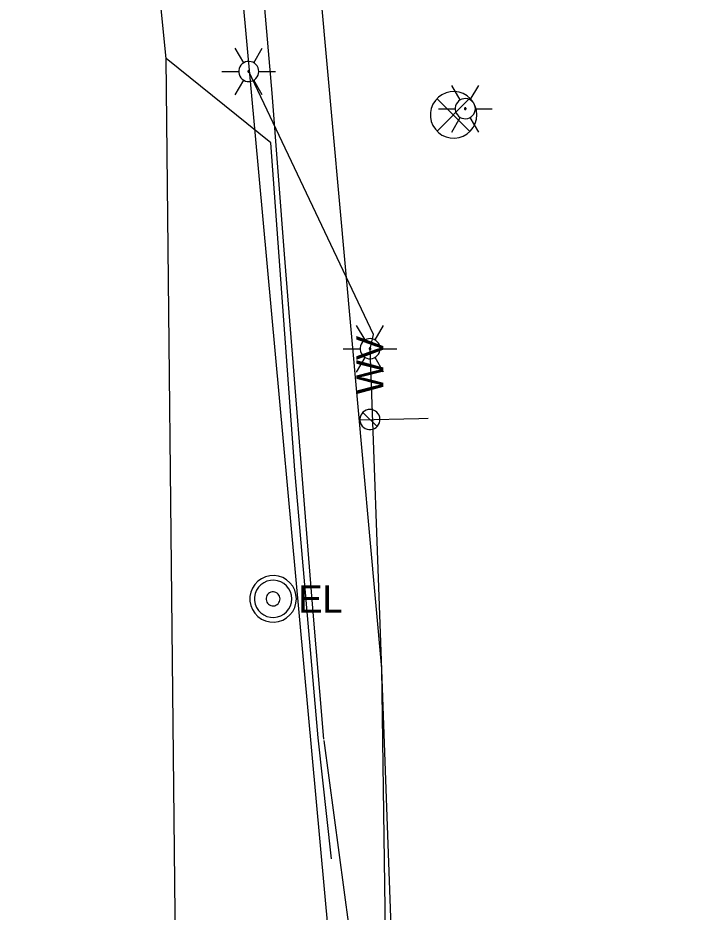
# Model space of a CAD drawing. Extents: x 600849 to 606371, y 330010 to 403088.
# Drawn here: x 605046.3 to 605141.7, y 332769.8 to 332896.4 of the extents above; entities that cross this region are included whole.
import ezdxf

# ---------------------------------------------------------------- set-up
doc = ezdxf.new("R2010")
doc.units = 0
for name, color, linetype in [('E_LTG', 7, 'Continuous'), ('E_LTG_CID', 7, 'Continuous'), ('E_SIG', 7, 'Continuous'), ('E_UTL_E', 7, 'Continuous'), ('E_UTL_G_UG', 7, 'Continuous'), ('E_UTL_SAN_UG', 7, 'Continuous'), ('E_UTL_TV_UG', 7, 'Continuous'), ('E_UTL_W', 7, 'Continuous'), ('E_UTL_W_UG', 7, 'Continuous')]:
    doc.layers.add(name, color=color, linetype=linetype)

msp = doc.modelspace()

# ---------------------------------------------------------------- linework, layer by layer
at = {"layer": 'E_LTG'}
for points in [[(605078.31, 332890.08), (605077.11, 332892.14)], [(605079.73, 332890.08), (605080.93, 332892.14)], [(605080.45, 332888.84), (605080.42, 332889.11), (605080.35, 332889.38), (605080.22, 332889.62), (605080.05, 332889.83), (605079.85, 332890.01), (605079.61, 332890.14), (605079.36, 332890.23), (605079.09, 332890.27), (605078.82, 332890.26), (605078.55, 332890.19), (605078.31, 332890.08), (605078.08, 332889.92), (605077.9, 332889.73), (605077.75, 332889.5), (605077.65, 332889.25), (605077.6, 332888.98), (605077.6, 332888.71), (605077.65, 332888.44), (605077.75, 332888.19), (605077.9, 332887.96), (605078.08, 332887.76), (605078.31, 332887.61), (605078.55, 332887.49), (605078.82, 332887.43), (605079.09, 332887.42), (605079.36, 332887.46), (605079.61, 332887.54), (605079.85, 332887.68), (605080.05, 332887.86), (605080.22, 332888.07), (605080.35, 332888.31), (605080.42, 332888.57), (605080.45, 332888.84)], [(605080.45, 332888.84), (605080.42, 332889.11), (605080.35, 332889.38), (605080.22, 332889.62), (605080.05, 332889.83), (605079.85, 332890.01), (605079.61, 332890.14), (605079.36, 332890.23), (605079.09, 332890.27), (605078.82, 332890.26), (605078.55, 332890.19), (605078.31, 332890.08), (605078.08, 332889.92), (605077.9, 332889.73), (605077.75, 332889.5), (605077.65, 332889.25), (605077.6, 332888.98), (605077.6, 332888.71), (605077.65, 332888.44), (605077.75, 332888.19), (605077.9, 332887.96), (605078.08, 332887.76), (605078.31, 332887.61), (605078.55, 332887.49), (605078.82, 332887.43), (605079.09, 332887.42), (605079.36, 332887.46), (605079.61, 332887.54), (605079.85, 332887.68), (605080.05, 332887.86), (605080.22, 332888.07), (605080.35, 332888.31), (605080.42, 332888.57), (605080.45, 332888.84)], [(605080.45, 332888.84), (605080.42, 332889.11), (605080.35, 332889.38), (605080.22, 332889.62), (605080.05, 332889.83), (605079.85, 332890.01), (605079.61, 332890.14), (605079.36, 332890.23), (605079.09, 332890.27), (605078.82, 332890.26), (605078.55, 332890.19), (605078.31, 332890.08), (605078.08, 332889.92), (605077.9, 332889.73), (605077.75, 332889.5), (605077.65, 332889.25), (605077.6, 332888.98), (605077.6, 332888.71), (605077.65, 332888.44), (605077.75, 332888.19), (605077.9, 332887.96), (605078.08, 332887.76), (605078.31, 332887.61), (605078.55, 332887.49), (605078.82, 332887.43), (605079.09, 332887.42), (605079.36, 332887.46), (605079.61, 332887.54), (605079.85, 332887.68), (605080.05, 332887.86), (605080.22, 332888.07), (605080.35, 332888.31), (605080.42, 332888.57), (605080.45, 332888.84)], [(605075.21, 332888.84), (605077.59, 332888.84)], [(605079.14, 332888.84), (605079.14, 332888.87), (605079.13, 332888.89), (605079.12, 332888.91), (605079.11, 332888.93), (605079.09, 332888.94), (605079.07, 332888.95), (605079.05, 332888.96), (605079.03, 332888.96), (605079, 332888.96), (605078.98, 332888.96), (605078.96, 332888.95), (605078.94, 332888.93), (605078.93, 332888.92), (605078.91, 332888.9), (605078.91, 332888.88), (605078.9, 332888.86), (605078.9, 332888.83), (605078.91, 332888.81), (605078.91, 332888.79), (605078.93, 332888.77), (605078.94, 332888.75), (605078.96, 332888.74), (605078.98, 332888.73), (605079, 332888.73), (605079.03, 332888.73), (605079.05, 332888.73), (605079.07, 332888.74), (605079.09, 332888.75), (605079.11, 332888.76), (605079.12, 332888.78), (605079.13, 332888.8), (605079.14, 332888.82), (605079.14, 332888.84)], [(605080.45, 332888.84), (605082.83, 332888.84)], [(605077.11, 332885.54), (605078.31, 332887.61)], [(605080.93, 332885.54), (605079.73, 332887.61)], [(605108.99, 332884.81), (605107.79, 332886.87)], [(605110.41, 332884.81), (605111.61, 332886.87)], [(605111.13, 332883.57), (605111.1, 332883.84), (605111.03, 332884.11), (605110.9, 332884.35), (605110.73, 332884.56), (605110.53, 332884.74), (605110.29, 332884.87), (605110.04, 332884.96), (605109.77, 332885), (605109.5, 332884.99), (605109.23, 332884.92), (605108.99, 332884.81), (605108.76, 332884.65), (605108.58, 332884.46), (605108.43, 332884.23), (605108.33, 332883.98), (605108.28, 332883.71), (605108.28, 332883.44), (605108.33, 332883.17), (605108.43, 332882.92), (605108.58, 332882.69), (605108.76, 332882.49), (605108.99, 332882.34), (605109.23, 332882.22), (605109.5, 332882.16), (605109.77, 332882.15), (605110.04, 332882.19), (605110.29, 332882.27), (605110.53, 332882.41), (605110.73, 332882.59), (605110.9, 332882.8), (605111.03, 332883.04), (605111.1, 332883.3), (605111.13, 332883.57)], [(605111.13, 332883.57), (605111.1, 332883.84), (605111.03, 332884.11), (605110.9, 332884.35), (605110.73, 332884.56), (605110.53, 332884.74), (605110.29, 332884.87), (605110.04, 332884.96), (605109.77, 332885), (605109.5, 332884.99), (605109.23, 332884.92), (605108.99, 332884.81), (605108.76, 332884.65), (605108.58, 332884.46), (605108.43, 332884.23), (605108.33, 332883.98), (605108.28, 332883.71), (605108.28, 332883.44), (605108.33, 332883.17), (605108.43, 332882.92), (605108.58, 332882.69), (605108.76, 332882.49), (605108.99, 332882.34), (605109.23, 332882.22), (605109.5, 332882.16), (605109.77, 332882.15), (605110.04, 332882.19), (605110.29, 332882.27), (605110.53, 332882.41), (605110.73, 332882.59), (605110.9, 332882.8), (605111.03, 332883.04), (605111.1, 332883.3), (605111.13, 332883.57)], [(605111.13, 332883.57), (605111.1, 332883.84), (605111.03, 332884.11), (605110.9, 332884.35), (605110.73, 332884.56), (605110.53, 332884.74), (605110.29, 332884.87), (605110.04, 332884.96), (605109.77, 332885), (605109.5, 332884.99), (605109.23, 332884.92), (605108.99, 332884.81), (605108.76, 332884.65), (605108.58, 332884.46), (605108.43, 332884.23), (605108.33, 332883.98), (605108.28, 332883.71), (605108.28, 332883.44), (605108.33, 332883.17), (605108.43, 332882.92), (605108.58, 332882.69), (605108.76, 332882.49), (605108.99, 332882.34), (605109.23, 332882.22), (605109.5, 332882.16), (605109.77, 332882.15), (605110.04, 332882.19), (605110.29, 332882.27), (605110.53, 332882.41), (605110.73, 332882.59), (605110.9, 332882.8), (605111.03, 332883.04), (605111.1, 332883.3), (605111.13, 332883.57)], [(605109.82, 332883.57), (605109.82, 332883.6), (605109.81, 332883.62), (605109.8, 332883.64), (605109.79, 332883.66), (605109.77, 332883.67), (605109.75, 332883.68), (605109.73, 332883.69), (605109.71, 332883.69), (605109.68, 332883.69), (605109.66, 332883.69), (605109.64, 332883.68), (605109.62, 332883.66), (605109.61, 332883.65), (605109.59, 332883.63), (605109.59, 332883.61), (605109.58, 332883.59), (605109.58, 332883.56), (605109.59, 332883.54), (605109.59, 332883.52), (605109.61, 332883.5), (605109.62, 332883.48), (605109.64, 332883.47), (605109.66, 332883.46), (605109.68, 332883.46), (605109.71, 332883.46), (605109.73, 332883.46), (605109.75, 332883.47), (605109.77, 332883.48), (605109.79, 332883.49), (605109.8, 332883.51), (605109.81, 332883.53), (605109.82, 332883.55), (605109.82, 332883.57)], [(605105.89, 332883.57), (605108.27, 332883.57)], [(605111.13, 332883.57), (605113.51, 332883.57)], [(605107.79, 332880.27), (605108.99, 332882.34)], [(605111.61, 332880.27), (605110.41, 332882.34)], [(605095.5, 332850.82), (605094.3, 332852.88)], [(605096.92, 332850.82), (605098.12, 332852.88)], [(605097.64, 332849.58), (605097.61, 332849.85), (605097.54, 332850.12), (605097.41, 332850.36), (605097.24, 332850.57), (605097.04, 332850.75), (605096.8, 332850.88), (605096.55, 332850.97), (605096.28, 332851.01), (605096.01, 332851), (605095.74, 332850.93), (605095.5, 332850.82), (605095.27, 332850.66), (605095.09, 332850.47), (605094.94, 332850.24), (605094.84, 332849.99), (605094.79, 332849.72), (605094.79, 332849.45), (605094.84, 332849.18), (605094.94, 332848.93), (605095.09, 332848.7), (605095.27, 332848.5), (605095.5, 332848.35), (605095.74, 332848.23), (605096.01, 332848.17), (605096.28, 332848.16), (605096.55, 332848.2), (605096.8, 332848.28), (605097.04, 332848.42), (605097.24, 332848.6), (605097.41, 332848.81), (605097.54, 332849.05), (605097.61, 332849.31), (605097.64, 332849.58)], [(605097.64, 332849.58), (605097.61, 332849.85), (605097.54, 332850.12), (605097.41, 332850.36), (605097.24, 332850.57), (605097.04, 332850.75), (605096.8, 332850.88), (605096.55, 332850.97), (605096.28, 332851.01), (605096.01, 332851), (605095.74, 332850.93), (605095.5, 332850.82), (605095.27, 332850.66), (605095.09, 332850.47), (605094.94, 332850.24), (605094.84, 332849.99), (605094.79, 332849.72), (605094.79, 332849.45), (605094.84, 332849.18), (605094.94, 332848.93), (605095.09, 332848.7), (605095.27, 332848.5), (605095.5, 332848.35), (605095.74, 332848.23), (605096.01, 332848.17), (605096.28, 332848.16), (605096.55, 332848.2), (605096.8, 332848.28), (605097.04, 332848.42), (605097.24, 332848.6), (605097.41, 332848.81), (605097.54, 332849.05), (605097.61, 332849.31), (605097.64, 332849.58)], [(605097.64, 332849.58), (605097.61, 332849.85), (605097.54, 332850.12), (605097.41, 332850.36), (605097.24, 332850.57), (605097.04, 332850.75), (605096.8, 332850.88), (605096.55, 332850.97), (605096.28, 332851.01), (605096.01, 332851), (605095.74, 332850.93), (605095.5, 332850.82), (605095.27, 332850.66), (605095.09, 332850.47), (605094.94, 332850.24), (605094.84, 332849.99), (605094.79, 332849.72), (605094.79, 332849.45), (605094.84, 332849.18), (605094.94, 332848.93), (605095.09, 332848.7), (605095.27, 332848.5), (605095.5, 332848.35), (605095.74, 332848.23), (605096.01, 332848.17), (605096.28, 332848.16), (605096.55, 332848.2), (605096.8, 332848.28), (605097.04, 332848.42), (605097.24, 332848.6), (605097.41, 332848.81), (605097.54, 332849.05), (605097.61, 332849.31), (605097.64, 332849.58)], [(605092.4, 332849.58), (605094.78, 332849.58)], [(605096.33, 332849.58), (605096.33, 332849.61), (605096.32, 332849.63), (605096.31, 332849.65), (605096.3, 332849.67), (605096.28, 332849.68), (605096.26, 332849.69), (605096.24, 332849.7), (605096.22, 332849.7), (605096.19, 332849.7), (605096.17, 332849.7), (605096.15, 332849.69), (605096.13, 332849.67), (605096.12, 332849.66), (605096.1, 332849.64), (605096.1, 332849.62), (605096.09, 332849.6), (605096.09, 332849.57), (605096.1, 332849.55), (605096.1, 332849.53), (605096.12, 332849.51), (605096.13, 332849.49), (605096.15, 332849.48), (605096.17, 332849.47), (605096.19, 332849.47), (605096.22, 332849.47), (605096.24, 332849.47), (605096.26, 332849.48), (605096.28, 332849.49), (605096.3, 332849.5), (605096.31, 332849.52), (605096.32, 332849.54), (605096.33, 332849.56), (605096.33, 332849.58)], [(605097.64, 332849.58), (605100.02, 332849.58)], [(605094.3, 332846.28), (605095.5, 332848.35)], [(605098.12, 332846.28), (605096.92, 332848.35)]]:
    msp.add_lwpolyline(points, dxfattribs=at)
at = {"layer": 'E_LTG_CID'}
msp.add_lwpolyline([(605093.78, 332739.36), (605099.35, 332763.84), (605096.21, 332849.58), (605096.68, 332851.6), (605079.02, 332888.84)], dxfattribs=at)
at = {"layer": 'E_SIG'}
for points in [[(605111.35, 332882.69), (605111.29, 332883.32), (605111.11, 332883.92), (605110.83, 332884.48), (605110.44, 332884.97), (605109.96, 332885.38), (605109.42, 332885.7), (605108.83, 332885.9), (605108.21, 332885.99), (605107.58, 332885.96), (605106.97, 332885.81), (605106.4, 332885.55), (605105.89, 332885.19), (605105.46, 332884.73), (605105.12, 332884.21), (605104.88, 332883.62), (605104.76, 332883.01), (605104.76, 332882.38), (605104.88, 332881.76), (605105.12, 332881.18), (605105.46, 332880.65), (605105.89, 332880.2), (605106.4, 332879.84), (605106.97, 332879.58), (605107.58, 332879.43), (605108.21, 332879.4), (605108.83, 332879.49), (605109.42, 332879.69), (605109.96, 332880.01), (605110.44, 332880.42), (605110.83, 332880.91), (605111.11, 332881.47), (605111.29, 332882.07), (605111.35, 332882.69)], [(605110.31, 332885.03), (605105.7, 332880.37)], [(605105.7, 332884.98), (605110.35, 332880.33)]]:
    msp.add_lwpolyline(points, dxfattribs=at)
at = {"layer": 'E_UTL_E'}
for points in [[(605085.77, 332814.16), (605085.71, 332814.78), (605085.54, 332815.38), (605085.25, 332815.94), (605084.86, 332816.43), (605084.39, 332816.84), (605083.84, 332817.16), (605083.25, 332817.36), (605082.63, 332817.45), (605082, 332817.42), (605081.39, 332817.27), (605080.82, 332817.01), (605080.31, 332816.65), (605079.88, 332816.2), (605079.54, 332815.67), (605079.31, 332815.09), (605079.19, 332814.47), (605079.19, 332813.84), (605079.31, 332813.23), (605079.54, 332812.64), (605079.88, 332812.12), (605080.31, 332811.66), (605080.82, 332811.3), (605081.39, 332811.04), (605082, 332810.89), (605082.63, 332810.86), (605083.25, 332810.95), (605083.84, 332811.15), (605084.39, 332811.47), (605084.86, 332811.88), (605085.25, 332812.37), (605085.54, 332812.93), (605085.71, 332813.53), (605085.77, 332814.16)], [(605085.77, 332814.16), (605085.71, 332814.78), (605085.54, 332815.38), (605085.25, 332815.94), (605084.86, 332816.43), (605084.39, 332816.84), (605083.84, 332817.16), (605083.25, 332817.36), (605082.63, 332817.45), (605082, 332817.42), (605081.39, 332817.27), (605080.82, 332817.01), (605080.31, 332816.65), (605079.88, 332816.2), (605079.54, 332815.67), (605079.31, 332815.09), (605079.19, 332814.47), (605079.19, 332813.84), (605079.31, 332813.23), (605079.54, 332812.64), (605079.88, 332812.12), (605080.31, 332811.66), (605080.82, 332811.3), (605081.39, 332811.04), (605082, 332810.89), (605082.63, 332810.86), (605083.25, 332810.95), (605083.84, 332811.15), (605084.39, 332811.47), (605084.86, 332811.88), (605085.25, 332812.37), (605085.54, 332812.93), (605085.71, 332813.53), (605085.77, 332814.16)], [(605085.11, 332814.16), (605085.06, 332814.66), (605084.92, 332815.14), (605084.69, 332815.58), (605084.38, 332815.98), (605084, 332816.31), (605083.57, 332816.56), (605083.09, 332816.72), (605082.6, 332816.79), (605082.1, 332816.77), (605081.61, 332816.65), (605081.15, 332816.44), (605080.74, 332816.15), (605080.4, 332815.79), (605080.12, 332815.37), (605079.94, 332814.9), (605079.84, 332814.41), (605079.84, 332813.9), (605079.94, 332813.41), (605080.12, 332812.95), (605080.4, 332812.52), (605080.74, 332812.16), (605081.15, 332811.87), (605081.61, 332811.66), (605082.1, 332811.54), (605082.6, 332811.52), (605083.09, 332811.59), (605083.57, 332811.75), (605084, 332812.01), (605084.38, 332812.33), (605084.69, 332812.73), (605084.92, 332813.17), (605085.06, 332813.66), (605085.11, 332814.16)], [(605085.11, 332814.16), (605085.06, 332814.66), (605084.92, 332815.14), (605084.69, 332815.58), (605084.38, 332815.98), (605084, 332816.31), (605083.57, 332816.56), (605083.09, 332816.72), (605082.6, 332816.79), (605082.1, 332816.77), (605081.61, 332816.65), (605081.15, 332816.44), (605080.74, 332816.15), (605080.4, 332815.79), (605080.12, 332815.37), (605079.94, 332814.9), (605079.84, 332814.41), (605079.84, 332813.9), (605079.94, 332813.41), (605080.12, 332812.95), (605080.4, 332812.52), (605080.74, 332812.16), (605081.15, 332811.87), (605081.61, 332811.66), (605082.1, 332811.54), (605082.6, 332811.52), (605083.09, 332811.59), (605083.57, 332811.75), (605084, 332812.01), (605084.38, 332812.33), (605084.69, 332812.73), (605084.92, 332813.17), (605085.06, 332813.66), (605085.11, 332814.16)], [(605083.46, 332814.16), (605083.44, 332814.34), (605083.39, 332814.52), (605083.3, 332814.69), (605083.19, 332814.84), (605083.05, 332814.96), (605082.88, 332815.06), (605082.7, 332815.12), (605082.52, 332815.14), (605082.33, 332815.14), (605082.15, 332815.09), (605081.98, 332815.01), (605081.82, 332814.9), (605081.69, 332814.77), (605081.59, 332814.61), (605081.52, 332814.43), (605081.49, 332814.25), (605081.49, 332814.06), (605081.52, 332813.88), (605081.59, 332813.7), (605081.69, 332813.54), (605081.82, 332813.41), (605081.98, 332813.3), (605082.15, 332813.22), (605082.33, 332813.18), (605082.52, 332813.17), (605082.7, 332813.19), (605082.88, 332813.25), (605083.05, 332813.35), (605083.19, 332813.47), (605083.3, 332813.62), (605083.39, 332813.79), (605083.44, 332813.97), (605083.46, 332814.16)], [(605083.46, 332814.16), (605083.44, 332814.34), (605083.39, 332814.52), (605083.3, 332814.69), (605083.19, 332814.84), (605083.05, 332814.96), (605082.88, 332815.06), (605082.7, 332815.12), (605082.52, 332815.14), (605082.33, 332815.14), (605082.15, 332815.09), (605081.98, 332815.01), (605081.82, 332814.9), (605081.69, 332814.77), (605081.59, 332814.61), (605081.52, 332814.43), (605081.49, 332814.25), (605081.49, 332814.06), (605081.52, 332813.88), (605081.59, 332813.7), (605081.69, 332813.54), (605081.82, 332813.41), (605081.98, 332813.3), (605082.15, 332813.22), (605082.33, 332813.18), (605082.52, 332813.17), (605082.7, 332813.19), (605082.88, 332813.25), (605083.05, 332813.35), (605083.19, 332813.47), (605083.3, 332813.62), (605083.39, 332813.79), (605083.44, 332813.97), (605083.46, 332814.16)]]:
    msp.add_lwpolyline(points, dxfattribs=at)
at = {"layer": 'E_UTL_G_UG'}
for points in [[(605067.35, 332890.68), (605061.21, 332951.97), (605055.05, 333004.59), (605053.86, 333028.21), (605052.5, 333057.99), (605051.57, 333081.36), (605049.66, 333125.99), (605048.74, 333179.43), (605048.99, 333222.62), (605050.19, 333270.55), (605050.67, 333295.8), (605051.06, 333345.63), (605051.56, 333380.01), (605052.25, 333442.11)], [(605090.74, 332777.32), (605088.87, 332794.46), (605085.56, 332832.37), (605082.16, 332878.72), (605067.35, 332890.68)], [(605069.91, 332651.64), (605069.52, 332684.31), (605067.35, 332890.68)], [(605090.74, 332777.32), (605090.74, 332777.32)]]:
    msp.add_lwpolyline(points, dxfattribs=at)
at = {"layer": 'E_UTL_SAN_UG'}
msp.add_line((605095.5, 332710.46), (605061.78, 333078.09), dxfattribs=at)
at = {"layer": 'E_UTL_TV_UG'}
for points in [[(605089.64, 332794.29), (605088.03, 332813.98), (605084.1, 332862.98), (605082.36, 332885.78), (605078.4, 332931.64), (605073.44, 332982.37), (605071.45, 333013.37), (605067.62, 333058.93), (605065.49, 333085.16), (605061.42, 333132.77), (605058.07, 333175.2), (605056.52, 333223.42), (605057.28, 333240.58), (605057.66, 333247.69), (605057.53, 333257.64), (605054.7, 333270.55), (605051.63, 333282.99), (605048.15, 333292.97), (605046.32, 333306.44), (605046.78, 333343.6), (605047.66, 333380.14), (605049.26, 333442.11)], [(605089.64, 332794.12), (605093.19, 332767.66), (605094.66, 332749.57), (605097.81, 332743.85), (605105.06, 332738.21), (605123.76, 332734.73), (605152.11, 332736.19), (605180.44, 332736.77), (605218.75, 332736.61), (605243.65, 332735.76), (605245.89, 332735.14), (605250.73, 332728.15), (605251.67, 332726.56)]]:
    msp.add_lwpolyline(points, dxfattribs=at)
at = {"layer": 'E_UTL_W'}
for points in [[(605096.19, 332840.98), (605095.92, 332840.95), (605095.66, 332840.88), (605095.42, 332840.75), (605095.21, 332840.59), (605095.03, 332840.38), (605094.89, 332840.15), (605094.8, 332839.89), (605094.77, 332839.62), (605094.78, 332839.35), (605094.84, 332839.09), (605094.95, 332838.84), (605095.11, 332838.62), (605095.31, 332838.43), (605095.54, 332838.29), (605095.79, 332838.19), (605096.05, 332838.13), (605096.33, 332838.13), (605096.59, 332838.19), (605096.84, 332838.29), (605097.07, 332838.43), (605097.27, 332838.62), (605097.42, 332838.84), (605097.54, 332839.09), (605097.6, 332839.35), (605097.61, 332839.62), (605097.58, 332839.89), (605097.49, 332840.15), (605097.35, 332840.38), (605097.17, 332840.59), (605096.96, 332840.75), (605096.72, 332840.88), (605096.46, 332840.95), (605096.19, 332840.98)], [(605097.2, 332838.55), (605095.18, 332840.56)]]:
    msp.add_lwpolyline(points, dxfattribs=at)
at = {"layer": 'E_UTL_W_UG'}
for p, q in [((605097.89, 332804.29), (605065.96, 333156.25)), ((605098.99, 332724.07), (605097.89, 332804.29))]:
    msp.add_line(p, q, dxfattribs=at)
msp.add_lwpolyline([(605094.69, 332839.52), (605103.1, 332839.72), (605104.42, 332839.75)], dxfattribs=at)

# ---------------------------------------------------------------- texts
at = {"layer": 'E_UTL_E'}
msp.add_text('EL', height=3.849, dxfattribs=at).set_placement((605086.04, 332812.21))
msp.add_text('EL', height=3.849, dxfattribs=at).set_placement((605086.04, 332812.21))
at = {"layer": 'E_UTL_W'}
msp.add_text('WV', height=3.85, rotation=90, dxfattribs=at).set_placement((605098.11, 332843.12))

doc.saveas('drawing.dxf')
